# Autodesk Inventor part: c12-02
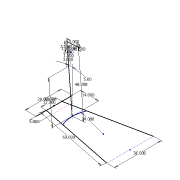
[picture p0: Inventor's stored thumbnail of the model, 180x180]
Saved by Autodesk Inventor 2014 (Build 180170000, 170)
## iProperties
Created: 2010-12
Part Number: c12-02
Material: Generic
Document SubType Name: Modeling
Designer: Thom Tremblay
Density: 1 g/cm^3
Appearance: Generic
Author: Thom Tremblay
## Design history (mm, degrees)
sketch "Sketch1" dims "d26" = 25.4
  geometry: L1 (355.6, 0)-(-355.6, 0); L2 (152.4, 0)-(457.2, 1493.209); L3 (-152.4, 0)-(-457.2, 1493.209); L4 (224.987, 355.6)-(-224.987, 355.6); L5 (457.2, 1493.209)-(-457.2, 1493.209); L6 (-178.324, 127)-(178.324, 127); A1 r 609.6 centre (0, 965.2) between (-234.567, 402.536) and (234.567, 402.536); 4 further points
  constraints: 12 end point, 8 point on line, 3 midpoint, 3 parallel, 2 point on circle, 2 vertical alignment, 1 centre point, 1 coincident, 1 equal length, 1 horizontal, 1 horizontal alignment, 1 tangent
  dimensions: "d0" = 711.2 distance of L1.start L1.end; "d1" = 1524 distance of L2.start L2.end; "d2" = 304.8 distance of L3.start L2.start; "d3" = 355.6 distance between parallel lines of L1 L4; "d4" = 914.4 distance of L2.end L3.end; "d8" = 127 distance between parallel lines of L6 L1; "d19" = 609.6 radius of A1
sketch "Sketch2"
  geometry: L1 (355.6, 0)-(355.6, 346.923); L2 (355.6, 0)-(249.34, 1214.561); L3 (249.34, 1214.561)-(502.373, 1236.698); L4 (303.898, 1028.106)-(300.387, 1068.232); L5 (306.233, 1086.772)-(385.066, 1180.722); L6 (402.31, 1189.698)-(442.435, 1193.209); A1 r 25.4 centre (325.691, 1070.446) between (306.233, 1086.772) and (300.387, 1068.232); A2 r 25.4 centre (404.523, 1164.395) between (402.31, 1189.698) and (385.066, 1180.722); 3 further points
  constraints: 12 end point, 4 point on circle, 4 point on line, 4 tangent, 2 centre point, 2 perpendicular, 1 equal radius, 1 parallel, 1 vertical, 1 other
  dimensions: "d5" = 1219.2 distance of L1.start L2.end; "d6" = 5 deg angle of L2 L1; "d11" = 254 distance of L2.end L3.end; "d20" = 50.8 distance of L4.start point (299.47, 1078.713); "d21" = 50.8 distance of point (391.829, 1188.781) L6.end; "d22" = 45 deg angle of L5 L4; "d23" = 190.5 distance from line of L3 L4.start; "d24" = 38.1 distance between parallel lines of L2 L4; "d25" = 38.1 distance between parallel lines of L3 L6; "d26" = 25.4 radius of A1
workplane "Work Plane1"
sketch "Sketch3" dims "d26" = 25.4
  geometry: L1 (224.987, 0)-(224.987, 1219.2) reference; L2 (186.887, 812.8)-(263.087, 812.8); 2 further points
  constraints: 2 end point, 1 midpoint, 1 perpendicular, 1 point on line
  dimensions: "d9" = 76.2 distance of L2.start L2.end; "d10" = 812.8 distance from line of L1.start L2
